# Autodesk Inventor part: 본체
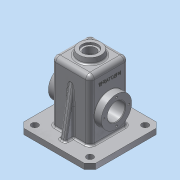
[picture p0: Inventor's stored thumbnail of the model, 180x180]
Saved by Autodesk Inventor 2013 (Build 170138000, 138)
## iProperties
Created: 2016-02
Part Number: 본체
Material: 알루미늄 6061
Document SubType Name: Modeling
Designer: dgall
Mass: 938.846 g
Surface Area: 1045.65 cm^2
Volume: 346.438 cm^3
Density: 2.71 g/cm^3
Author: dgall
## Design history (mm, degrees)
sketch "스케치1"
  geometry: L1 (-35, 35)-(35, 35); L2 (35, 35)-(35, -35); L3 (35, -35)-(-35, -35); L4 (-35, -35)-(-35, 35); 1 further point
  constraints: 8 end point, 2 parallel, 1 horizontal, 1 perpendicular
  dimensions: "d0" = 70 distance of L1.end L2.end; "d2" = 70 distance of L1.start L1.end; "d3" = 35 distance from line of point (0, 0) L1; "d4" = 35 distance from line of point (0, 0) L2
extrude "돌출1" new body sketch "스케치1" distance "d5" = 120; taper "d6" = 0 deg
feature "쉘1" dims "d7" = 5
fillet "모깎기1" dims "d8" = 8
fillet "모깎기2" dims "d9" = 8
fillet "모깎기3" dims "d10" = 3
fillet "모깎기4" dims "d11" = 3
sketch "스케치2"
  geometry: L1 (-35, 27)-(-35, -27) reference; L2 (-27, -35)-(27, -35) reference; L3 (35, -27)-(35, 27) reference; L4 (27, 35)-(-27, 35) reference; L5 (-65, 65)-(65, 65); L6 (65, 65)-(65, -65); L7 (65, -65)-(-65, -65); L8 (-65, -65)-(-65, 65); A1 r 8 centre (-27, 27) between (-27, 35) and (-35, 27) reference; A2 r 8 centre (-27, -27) between (-35, -27) and (-27, -35) reference; A3 r 8 centre (27, -27) between (27, -35) and (35, -27) reference; A4 r 8 centre (27, 27) between (35, 27) and (27, 35) reference; 1 further point
  constraints: 8 end point, 2 parallel, 1 horizontal, 1 perpendicular
  dimensions: "d12" = 130 distance of L5.start L5.end; "d14" = 130 distance of L5.end L6.end; "d15" = 65 distance from line of point (0, 0) L6; "d16" = 65 distance from line of point (0, 0) L5
extrude "돌출2" join sketch "스케치2" distance "d17" = 10; taper "d18" = 0 deg
sketch "스케치3"
  geometry: L1 (-35, 10)-(-35, 112) reference; L2 (65, 10)-(-65, 10) reference; L3 (-50, 10)-(-35, 95.069); L4 (-65, 0)-(-65, 10) reference; 1 further point
  constraints: 2 end point, 2 point on line
  dimensions: "d19" = 15 distance from line of L3.start L4; "d20" = 10 deg angle of L4 L3
feature "리브1" sketch "스케치3" dims "d21" = 1, "d22" = 10, "d23" = 0, "d24" = 0, "d25" = 1, "d26" = 1
sketch "스케치4"
  geometry: L1 (35, 10)-(27, 10) reference; L2 (27, 10)-(27, 112) reference; L3 (35, 112)-(27, 112) reference; L4 (35, 112)-(35, 10) reference; L5 (65, 10)-(-65, 10) reference; L6 (35, 95.069)-(50, 10); L7 (65, 0)-(65, 10) reference; 1 further point
  constraints: 2 end point, 2 point on line
  dimensions: "d27" = 15 distance from line of L7 L6.end; "d28" = 10 deg angle of L7 L6
feature "리브2" sketch "스케치4" dims "d29" = 1, "d30" = 10, "d31" = 0, "d32" = 0, "d33" = 1, "d34" = 1
node "작업 평면1"
sketch "스케치5"
  geometry: C1 r 27.5 at (0, 55); 1 further point
  constraints: 1 centre point
  dimensions: "d36" = 55 diameter of C1; "d38" = 55 distance of point (0, 0) C1.centre; "d39" = 0 horizontal distance of point (0, 0) C1.centre
extrude "돌출3" join sketch "스케치5" stored distance "d40" = 10; taper "d41" = 0 deg
node "작업 평면2"
sketch "스케치6"
  geometry: C1 r 27.5 at (0, 55); 1 further point
  constraints: 1 centre point
  dimensions: "d43" = 55 diameter of C1; "d45" = 55 distance of point (0, 0) C1.centre; "d46" = 0 horizontal distance of point (0, 0) C1.centre
extrude "돌출4" join sketch "스케치6" stored distance "d47" = 10; taper "d48" = 0 deg
sketch "스케치7"
  geometry: C1 r 27.5 at (0, 0) reference; C2 r 16 at (0, 0); 1 further point
  constraints: 1 centre point, 1 coincident
  dimensions: "d49" = 32 diameter of C2
extrude "돌출5" cut sketch "스케치7" stored distance "d51" = 10; taper "d52" = 0 deg
sketch "스케치8"
  geometry: L1 (30, 112)-(30, 0) reference; L2 (-30, 0)-(-30, 112) reference; L3 (-48, 27.5)-(-48, 82.5) reference; L4 (48, 82.5)-(48, 27.5) reference; L5 (78.131, 55)-(-93.042, 55); L6 (30, 82.5)-(23, 75.5); L7 (23, 75.5)-(23, 55); L8 (30, 82.5)-(30, 55); L9 (23, 55)-(30, 55); 1 further point
  constraints: 10 end point, 4 point on line, 2 perpendicular, 1 collinear
  dimensions: "d53" = 55 distance from line of point (0, 0) L5; "d54" = 7 distance between parallel lines of L7 L1; "d55" = 55 diameter of L6.start L5; "d56" = 135 deg angle of L6 L7
revolve "회전1" sketch "스케치8" stored, may be unused: angle "d57" = 90 deg
sketch "스케치9"
  geometry: C1 r 16 at (0, 0) reference; 1 further point
extrude "돌출6" cut sketch "스케치9" stored distance "d58" = 10; taper "d59" = 0 deg
sketch "스케치10"
  geometry: L1 (71.465, 55)-(-61.462, 55); L2 (-30, 0)-(-30, 112) reference; L3 (-23, 55)-(-23, 34.5); L4 (-23, 34.5)-(-30, 27.5); L5 (-30, 55)-(-30, 27.5); L6 (-30, 55)-(-23, 55); 1 further point
  constraints: 10 end point, 4 point on line, 2 collinear, 1 horizontal, 1 perpendicular
  dimensions: "d60" = 55 distance from line of L1 point (0, 0); "d62" = 135 deg angle of L3 L4; "d63" = 55 diameter of L4.end L1; "d64" = 7 distance between parallel lines of L2 L3
revolve "회전2" sketch "스케치10" stored, may be unused: angle "d65" = 90 deg
sketch "스케치11"
  geometry: C1 r 16 at (0, 0) reference; 1 further point
extrude "돌출7" cut sketch "스케치11" stored distance "d66" = 10; taper "d67" = 0 deg
node "작업 평면3"
sketch "스케치12"
  geometry: C1 r 20 at (0, 0); 1 further point
  constraints: 1 centre point, 1 coincident
  dimensions: "d69" = 40 diameter of C1
extrude "돌출8" join sketch "스케치12" stored distance "d71" = 10; taper "d72" = 10 deg
sketch "스케치13"
  geometry: C1 r 20 at (0, 0) reference; C2 r 14 at (0, 0)
  constraints: 1 centre point, 1 coincident
  dimensions: "d73" = 28 diameter of C2
extrude "돌출9" cut sketch "스케치13" distance "d75" = 4; taper "d76" = 0 deg
sketch "스케치14"
  geometry: C1 r 14 at (0, 0) reference; C2 r 10.5 at (0, 0)
  constraints: 1 centre point, 1 coincident
  dimensions: "d77" = 21 diameter of C2
extrude "돌출10" cut sketch "스케치14" stored distance "d79" = 4; taper "d80" = 0 deg
chamfer "모따기1" distance "d81" = 10; stored, may be unused: second distance "d82" = 2, angle "d83" = 45 deg
sketch "스케치15"
  geometry: L1 (-65, 55)-(-65, -55) reference; L2 (-55, -65)-(55, -65) reference; L3 (65, -55)-(65, 55) reference; L4 (55, 65)-(-55, 65) reference; C1 r 6 at (-50, 50); C2 r 6 at (50, 50); C3 r 6 at (50, -50); C4 r 6 at (-50, -50); 1 further point
  constraints: 4 centre point
  dimensions: "d84" = 15 distance from line of C2.centre L3; "d85" = 15 distance from line of C2.centre L4; "d86" = 15 distance from line of C1.centre L4; "d87" = 15 distance from line of L1 C1.centre; "d88" = 15 distance from line of C4.centre L1; "d89" = 15 distance from line of L2 C4.centre; "d90" = 15 distance from line of L2 C3.centre; "d91" = 15 distance from line of C3.centre L3; "d92" = 12 diameter of C1; "d93" = 12 diameter of C2; "d94" = 12 diameter of C3; "d95" = 12 diameter of C4
extrude "돌출11" cut sketch "스케치15" stored distance "d96" = 4; taper "d97" = 0 deg
sketch "스케치16" dims "d98" = 45
  geometry: L1 (0, 0)-(-22.5, 0); C1 r 16 at (0, 0) reference; C2 r 27.5 at (0, 0) reference; C3 r 2 at (-22.5, 0); C4 r 2 at (0, -22.5); C5 r 2 at (22.5, 0); C6 r 2 at (0, 22.5); 1 further point
  constraints: 4 centre point, 2 coincident, 2 end point, 1 horizontal, 1 horizontal alignment, 11 other
  dimensions: "d100" = 4 diameter of C3; "d103" = 360 deg dimension on C1.centre C3.centre (derived)
hole "구멍1" sketch "스케치16" at (0, -22.5), (-22.5, 0), (0, 22.5), (22.5, 0) diameter "d105" = 3.459; stored, may be unused: countersink angle "d109" = 90 deg, drill point angle "d111" = 118 deg; dims "d106" = 8, "d107" = 4, "d108" = 2, "d110" = 10
fillet "모깎기5" dims "d112" = 3
fillet "모깎기6" dims "d113" = 3
fillet "모깎기7" dims "d114" = 3
fillet "모깎기8" dims "d115" = 0.5
fillet "모깎기9" dims "d116" = 0.5
sketch "스케치17"
  geometry: L1 (9, 7)-(9, 47); L2 (9, 47)-(15, 47); L3 (15, 47)-(15, 7); L4 (15, 7)-(9, 7); L5 (12, 47)-(12, 7); L6 (9, 27)-(15, 27); L7 (-18, 7)-(-18, 47) reference; 1 further point
  constraints: 4 end point, 4 midpoint, 2 other
  dimensions: "d117" = 0 distance from line of point (112, 27) L6; "d118" = 30 distance between parallel lines of L5 L7; "d119" = 6 distance between parallel lines of L3 L1; "d120" = 40 distance of L2.end L3.end
extrude "돌출12" join sketch "스케치17" distance "d121" = 0.5; taper "d122" = 0 deg
chamfer "모따기2" distance "d123" = 1; stored, may be unused: second distance "d124" = 2, angle "d125" = 45 deg
node "솔리드1"
mirror "대칭1"
node "투영된 루프1"
node "작업 평면4"
other parameters: "d35" = -48, "d42" = 48
